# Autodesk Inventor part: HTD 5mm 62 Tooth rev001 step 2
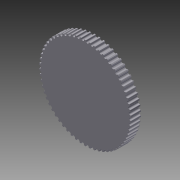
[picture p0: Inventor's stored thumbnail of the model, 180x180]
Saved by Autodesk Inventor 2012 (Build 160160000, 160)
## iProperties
Created: 2011-12
Part Number: HTD 5mm 62 Tooth rev001 step 2
Document SubType Name: Modeling
Designer: Alex
Density: 2.71 g/cm^3
Material: Aluminum-6061
Mass: 204.396 g
Surface Area: 191.006 cm^2
Volume: 75.423 cm^3
Author: Alex
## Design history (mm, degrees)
sketch "Body"
  geometry: C1 r 48.768 at (0, 0); 1 further point
  constraints: 1 centre point, 1 coincident
  dimensions: "d127" = 97.536 diameter of C1
extrude "Extrusion1" new body sketch "Body" distance "d128" = 10.5664; taper "d129" = 0 deg
sketch "62 Teeth"
  geometry: L1 (0, 0)-(0, 28.7); L2 (-28.232, 0)-(27.326, 0); L3 (1.288, 25.396)-(0, 0); L4 (-1.288, 25.396)-(0, 0); L5 (2.139, 46.688)-(2.595, 46.664); L6 (0.937, 48.357)-(1, 47.765); L7 (3.96, 48.203)-(3.837, 47.621); L8 (0, 0)-(-52.452, 0); L9 (-0.937, 48.357)-(-1, 47.765); L10 (-2.595, 46.664)-(-2.139, 46.688); L11 (-3.96, 48.203)-(-3.837, 47.621); L12 (-5.825, 48.014)-(-5.827, 47.419); L13 (-7.303, 46.162)-(-6.851, 46.232); L14 (-8.816, 47.556)-(-8.635, 46.988); L15 (-10.652, 47.178)-(-10.595, 46.586); L16 (-11.936, 45.187)-(-11.493, 45.301); L17 (-13.582, 46.42)-(-13.345, 45.874); L18 (-15.37, 45.859)-(-15.253, 45.275); L19 (-16.446, 43.747)-(-16.017, 43.906); L20 (-18.208, 44.807)-(-17.917, 44.288); L21 (-19.931, 44.068)-(-19.756, 43.499); L22 (-20.787, 41.859)-(-20.377, 42.06); L23 (-22.648, 42.735)-(-22.306, 42.248); L24 (-24.287, 41.826)-(-24.055, 41.278); L25 (-24.916, 39.541)-(-24.528, 39.783); L26 (-26.855, 40.225)-(-26.466, 39.775); L27 (-28.394, 39.154)-(-28.107, 38.632); L28 (-28.788, 36.818)-(-28.427, 37.098); L29 (-30.787, 37.302)-(-30.354, 36.894); L30 (-32.209, 36.081)-(-31.872, 35.59); L31 (-32.365, 33.716)-(-32.034, 34.031); L32 (-34.403, 33.996)-(-33.931, 33.633); L33 (-35.694, 32.637)-(-35.309, 32.183); L34 (-35.61, 30.269)-(-35.312, 30.616); L35 (-37.666, 30.341)-(-37.159, 30.028); L36 (-38.813, 28.858)-(-38.384, 28.446); L37 (-38.49, 26.511)-(-38.229, 26.886); L38 (-40.542, 26.374)-(-40.006, 26.115); L39 (-41.533, 24.784)-(-41.064, 24.417); L40 (-40.974, 22.481)-(-40.753, 22.881); L41 (-43.002, 22.137)-(-42.443, 21.933); L42 (-43.828, 20.455)-(-43.324, 20.137); L43 (-43.039, 18.221)-(-42.858, 18.641); L44 (-45.021, 17.673)-(-44.444, 17.527); L45 (-45.672, 15.916)-(-45.139, 15.651); L46 (-44.661, 13.773)-(-44.524, 14.209); L47 (-46.578, 13.028)-(-45.989, 12.941); L48 (-47.048, 11.213)-(-46.491, 11.004); L49 (-45.825, 9.184)-(-45.733, 9.632); L50 (-47.657, 8.249)-(-47.063, 8.222); L51 (-47.941, 6.396)-(-47.366, 6.244); L52 (-46.519, 4.501)-(-46.473, 4.956); L53 (-48.247, 3.385)-(-47.653, 3.418); L54 (-48.342, 1.513)-(-47.754, 1.42); L55 (-46.736, -0.229)-(-46.736, 0.229); L56 (-48.342, -1.513)-(-47.754, -1.42); L57 (-48.247, -3.385)-(-47.653, -3.418); L58 (-46.473, -4.956)-(-46.519, -4.501); L59 (-47.941, -6.396)-(-47.366, -6.244); L60 (-47.657, -8.249)-(-47.063, -8.222); L61 (-45.733, -9.632)-(-45.825, -9.184); L62 (-47.048, -11.213)-(-46.491, -11.004); L63 (-46.578, -13.028)-(-45.989, -12.941); L64 (-44.524, -14.209)-(-44.661, -13.773)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; A1 r 48.768 centre (0, 0) between (4.449, 48.565) and (0.487, 48.766); A2 r 0.457 centre (0.483, 48.308) between (0.937, 48.357) and (0.487, 48.766); A3 r 0.457 centre (4.407, 48.109) between (4.449, 48.565) and (3.96, 48.203); A4 r 1.207 centre (2.657, 47.869) between (2.595, 46.664) and (3.837, 47.621); A5 r 1.207 centre (2.2, 47.893) between (1, 47.765) and (2.139, 46.688); A6 r 48.768 centre (0, 0) between (-0.487, 48.766) and (-4.449, 48.565); A7 r 0.457 centre (-0.483, 48.308) between (-0.487, 48.766) and (-0.937, 48.357); A8 r 1.207 centre (-2.2, 47.893) between (-2.139, 46.688) and (-1, 47.765); A9 r 1.207 centre (-2.657, 47.869) between (-3.837, 47.621) and (-2.595, 46.664); A10 r 0.457 centre (-4.407, 48.109) between (-3.96, 48.203) and (-4.449, 48.565); A11 r 48.768 centre (0, 0) between (-5.418, 48.466) and (-9.339, 47.865); A12 r 0.457 centre (-5.367, 48.012) between (-5.418, 48.466) and (-5.825, 48.014); A13 r 1.207 centre (-7.034, 47.424) between (-6.851, 46.232) and (-5.827, 47.419); A14 r 1.207 centre (-7.486, 47.355) between (-8.635, 46.988) and (-7.303, 46.162); A15 r 0.457 centre (-9.252, 47.417) between (-8.816, 47.556) and (-9.339, 47.865); A16 r 48.768 centre (0, 0) between (-10.294, 47.669) and (-14.134, 46.675); A17 r 0.457 centre (-10.197, 47.222) between (-10.294, 47.669) and (-10.652, 47.178); A18 r 1.207 centre (-11.796, 46.469) between (-11.493, 45.301) and (-10.595, 46.586); A19 r 1.207 centre (-12.238, 46.355) between (-13.345, 45.874) and (-11.936, 45.187); A20 r 0.457 centre (-14.001, 46.237) between (-13.582, 46.42) and (-14.134, 46.675); A21 r 48.768 centre (0, 0) between (-15.063, 46.383) and (-18.783, 45.006); A22 r 0.457 centre (-14.922, 45.948) between (-15.063, 46.383) and (-15.37, 45.859); A23 r 1.207 centre (-16.436, 45.038) between (-16.017, 43.906) and (-15.253, 45.275); A24 r 1.207 centre (-16.865, 44.879) between (-17.917, 44.288) and (-16.446, 43.747); A25 r 0.457 centre (-18.607, 44.584) between (-18.208, 44.807) and (-18.783, 45.006); A26 r 48.768 centre (0, 0) between (-19.679, 44.621) and (-23.24, 42.874); A27 r 0.457 centre (-19.494, 44.203) between (-19.679, 44.621) and (-19.931, 44.068); A28 r 1.207 centre (-20.908, 43.144) between (-20.377, 42.06) and (-19.756, 43.499); A29 r 1.207 centre (-21.319, 42.942) between (-22.306, 42.248) and (-20.787, 41.859); A30 r 0.457 centre (-23.022, 42.472) between (-22.648, 42.735) and (-23.24, 42.874); A31 r 48.768 centre (0, 0) between (-24.092, 42.402) and (-27.458, 40.303); A32 r 0.457 centre (-23.866, 42.004) between (-24.092, 42.402) and (-24.287, 41.826); A33 r 1.207 centre (-25.166, 40.807) between (-24.528, 39.783) and (-24.055, 41.278); A34 r 1.207 centre (-25.554, 40.565) between (-26.466, 39.775) and (-24.916, 39.541); A35 r 0.457 centre (-27.201, 39.925) between (-26.855, 40.225) and (-27.458, 40.303); A36 r 48.768 centre (0, 0) between (-28.258, 39.747) and (-31.395, 37.319); A37 r 0.457 centre (-27.993, 39.374) between (-28.258, 39.747) and (-28.394, 39.154); A38 r 1.207 centre (-29.165, 38.052) between (-28.427, 37.098) and (-28.107, 38.632); A39 r 1.207 centre (-29.527, 37.772) between (-30.354, 36.894) and (-28.788, 36.818); A40 r 0.457 centre (-31.101, 36.969) between (-30.787, 37.302) and (-31.395, 37.319); A41 r 48.768 centre (0, 0) between (-32.134, 36.684) and (-35.009, 33.951); A42 r 0.457 centre (-31.833, 36.34) between (-32.134, 36.684) and (-32.209, 36.081); A43 r 1.207 centre (-32.865, 34.906) between (-32.034, 34.031) and (-31.872, 35.59); A44 r 1.207 centre (-33.196, 34.591) between (-33.931, 33.633) and (-32.365, 33.716); A45 r 0.457 centre (-34.681, 33.633) between (-34.403, 33.996) and (-35.009, 33.951); A46 r 48.768 centre (0, 0) between (-35.681, 33.245) and (-38.264, 30.235); A47 r 0.457 centre (-35.346, 32.933) between (-35.681, 33.245) and (-35.694, 32.637); A48 r 1.207 centre (-36.228, 31.402) between (-35.312, 30.616) and (-35.309, 32.183); A49 r 1.207 centre (-36.526, 31.055) between (-37.159, 30.028) and (-35.61, 30.269); A50 r 0.457 centre (-37.906, 29.951) between (-37.666, 30.341) and (-38.264, 30.235); A51 r 48.768 centre (0, 0) between (-38.861, 29.464) and (-41.127, 26.209); A52 r 0.457 centre (-38.497, 29.188) between (-38.861, 29.464) and (-38.813, 28.858); A53 r 1.207 centre (-39.219, 27.576) between (-38.229, 26.886) and (-38.384, 28.446); A54 r 1.207 centre (-39.48, 27.2) between (-40.006, 26.115) and (-38.49, 26.511); A55 r 0.457 centre (-40.741, 25.963) between (-40.542, 26.374) and (-41.127, 26.209); A56 r 48.768 centre (0, 0) between (-41.642, 25.382) and (-43.567, 21.913); A57 r 0.457 centre (-41.252, 25.144) between (-41.642, 25.382) and (-41.533, 24.784); A58 r 1.207 centre (-41.807, 23.466) between (-40.753, 22.881) and (-41.064, 24.417); A59 r 1.207 centre (-42.029, 23.067) between (-42.443, 21.933) and (-40.974, 22.481); A60 r 0.457 centre (-43.159, 21.708) between (-43.002, 22.137) and (-43.567, 21.913); A61 r 48.768 centre (0, 0) between (-43.996, 21.039) and (-45.561, 17.393); A62 r 0.457 centre (-43.584, 20.841) between (-43.996, 21.039) and (-43.828, 20.455); A63 r 1.207 centre (-43.967, 19.116) between (-42.858, 18.641) and (-43.324, 20.137); A64 r 1.207 centre (-44.147, 18.696) between (-44.444, 17.527) and (-43.039, 18.221)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; 3 further points
  constraints: 620 point on circle, 382 end point, 310 centre point, 6 symmetric about line, 4 tangent, 2 perpendicular, 2 point on line, 1 coincident, 1 vertical, 1304 other
  dimensions: "d0" = 97.536 diameter of A1; "d4" = 0.9144 diameter of A2; "d27" = 62.32514 dimension on L3 L1; "d46" = 2.032 distance edge to line of A1 L5; "d66" = 0.4826 distance from line of A2.centre L1; "d82" = 0.2286 distance from line of L3 A5.centre; "d125" = 360 deg dimension on point (0, 0) A1.start (derived)
extrude "Extrusion2" cut sketch "62 Teeth" stored distance "d130" = 0; taper "d131" = 0 deg
body "Solid1"
other parameters: "d0" = 97.536, "d4" = 0.9144, "d27" = 62.32514, "d46" = 2.032, "d47" = 2.413, "d66" = 0.4826, "d82" = 0.2286, "d125" = 360 deg (derived)
